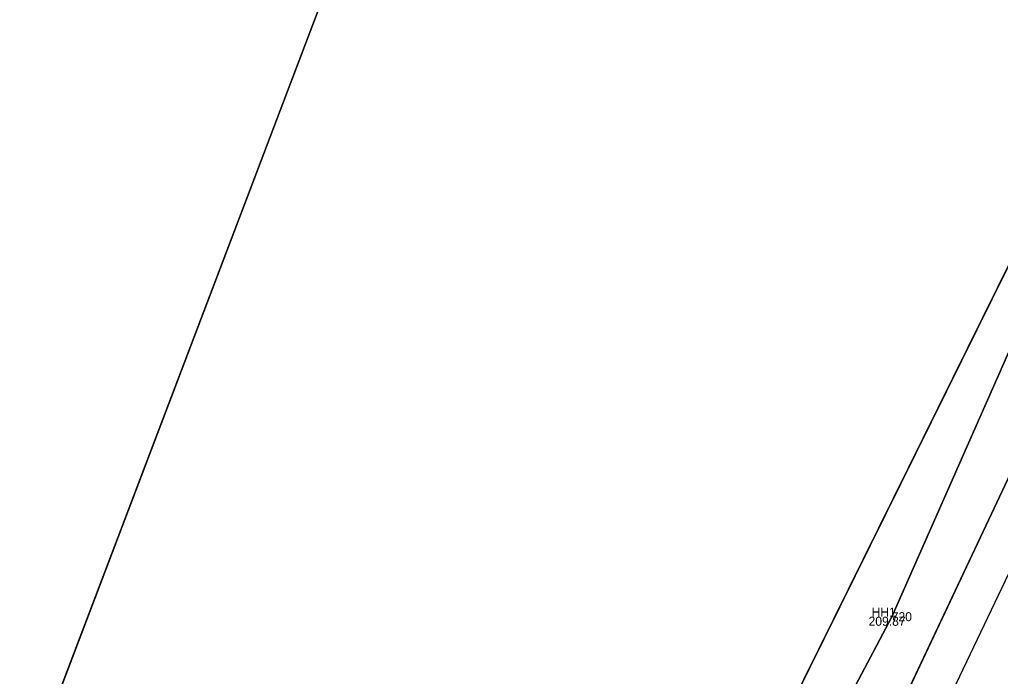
# Model space of a CAD drawing. Extents: x -263091 to -262565, y -1238731 to -1237092.
# Drawn here: x -262808.34 to -262786.65, y -1237663.71 to -1237649.19 of the extents above; entities that cross this region are included whole.
import ezdxf

# ---------------------------------------------------------------- set-up
doc = ezdxf.new("R2010")
doc.units = 0
for name, color, linetype in [('01_Hrana_betónu', 7, 'Continuous'), ('02_Oplotenie', 7, 'Continuous'), ('05_Hrana_terénu', 7, 'Continuous'), ('11_Hranica_KN', 7, 'Continuous'), ('Groma (21)', 7, 'Continuous'), ('Groma (22)', 7, 'Continuous'), ('Groma (23)', 7, 'Continuous'), ('Groma (24)', 7, 'Continuous'), ('U005_Betónové_panely', 7, 'Continuous'), ('U005_Zeleň_mimo', 7, 'Continuous'), ('U005_Zeleň_vnútro', 7, 'Continuous'), ('U005_Zeleň_zatrávňovač', 7, 'Continuous')]:
    doc.layers.add(name, color=color, linetype=linetype)

msp = doc.modelspace()

# ---------------------------------------------------------------- linework, layer by layer
at = {"layer": '01_Hrana_betónu'}
for points in [[(-262744.671, -1237314.693), (-262744.322, -1237332.28), (-262744.032, -1237356.103), (-262743.621, -1237377.876), (-262743.427, -1237401.834), (-262743.334, -1237423.507), (-262743.665, -1237455.163), (-262743.89, -1237458.66), (-262743.816, -1237479.543), (-262744.125, -1237500.374), (-262744.256, -1237524.891), (-262744.407, -1237545.149), (-262744.747, -1237556.085), (-262745.544, -1237564.593), (-262746.648, -1237572.023), (-262748.879, -1237581.03), (-262752.099, -1237589.665), (-262756.673, -1237599.828), (-262765.314, -1237617.226), (-262775.804, -1237639.013), (-262783.576, -1237655.372), (-262792.033, -1237673.09)], [(-262792.676, -1237672.47), (-262784.421, -1237654.971), (-262776.677, -1237638.569), (-262766.087, -1237616.912), (-262757.487, -1237599.378), (-262752.942, -1237589.379), (-262749.712, -1237580.796), (-262747.504, -1237571.715), (-262746.486, -1237564.414), (-262745.673, -1237555.98), (-262745.336, -1237545.322), (-262745.216, -1237524.737), (-262745.016, -1237500.506), (-262744.745, -1237479.418), (-262744.873, -1237458.479), (-262744.515, -1237455.206), (-262744.284, -1237423.517), (-262744.408, -1237401.828), (-262744.521, -1237377.717), (-262744.916, -1237356.111), (-262745.155, -1237332.402), (-262745.296, -1237327.881), (-262745.213, -1237324.651), (-262745.472, -1237315.175)]]:
    msp.add_lwpolyline(points, dxfattribs=at)
at = {"layer": '02_Oplotenie'}
msp.add_lwpolyline([(-262793.971, -1237669.784), (-262786.051, -1237653.784), (-262778.339, -1237638.096), (-262767.839, -1237615.998), (-262759.49, -1237598.413), (-262754.828, -1237588.44), (-262751.768, -1237579.927), (-262749.971, -1237571.226), (-262749.021, -1237564.318), (-262748.215, -1237555.413), (-262747.787, -1237545.2), (-262747.818, -1237524.565), (-262747.681, -1237500.551), (-262747.391, -1237479.445), (-262747.231, -1237460.146), (-262746.875, -1237423.458), (-262747.304, -1237401.954), (-262748.156, -1237377.36), (-262748.89, -1237356.224), (-262749.247, -1237329.045)], dxfattribs=at)
at = {"layer": '05_Hrana_terénu'}
msp.add_lwpolyline([(-262746.684, -1237500.449), (-262746.883, -1237524.672), (-262746.96, -1237545.219), (-262747.259, -1237555.728), (-262748.105, -1237564.398), (-262749.066, -1237571.186), (-262750.795, -1237580.085), (-262754.134, -1237588.771), (-262758.577, -1237598.887), (-262767.121, -1237616.464), (-262785.488, -1237654.334), (-262789.051, -1237662.387), (-262794.016, -1237671.765)], dxfattribs=at)
at = {"layer": '11_Hranica_KN'}
msp.add_lwpolyline([(-262808.336, -1237666.357), (-262793.39, -1237627.04), (-262791.777, -1237622.951)], dxfattribs=at)
at = {"layer": 'Groma (21)'}
msp.add_circle((-262789.051, -1237662.387), 0.01, dxfattribs=at)
at = {"layer": 'U005_Betónové_panely'}
for points in [[(-262783.28, -1237678.88), (-262786.97, -1237677.03), (-262787.74, -1237676.65), (-262788.17, -1237676.43), (-262788.97, -1237676.03), (-262792.52, -1237674.26), (-262791.95, -1237673.18), (-262792.03, -1237673.09), (-262792.68, -1237672.47), (-262784.42, -1237654.97), (-262776.68, -1237638.57), (-262766.09, -1237616.91), (-262757.49, -1237599.38), (-262752.94, -1237589.38), (-262749.71, -1237580.8), (-262747.5, -1237571.72), (-262746.49, -1237564.41), (-262745.67, -1237555.98), (-262745.34, -1237545.32), (-262745.22, -1237524.74), (-262745.02, -1237500.51)], [(-262747.21, -1237604.2), (-262756.24, -1237623.63), (-262765.96, -1237644.11), (-262773.68, -1237660.32), (-262779.99, -1237673.1), (-262781.45, -1237675.8), (-262782.33, -1237677.96), (-262782.75, -1237677.74), (-262783.28, -1237678.88), (-262786.97, -1237677.03), (-262787.74, -1237676.65), (-262788.17, -1237676.43), (-262788.97, -1237676.03), (-262792.52, -1237674.26), (-262791.95, -1237673.18), (-262792.03, -1237673.09), (-262792.68, -1237672.47), (-262784.42, -1237654.97), (-262776.68, -1237638.57), (-262766.09, -1237616.91)]]:
    msp.add_lwpolyline(points, dxfattribs=at)
at = {"layer": 'U005_Zeleň_mimo'}
msp.add_lwpolyline([(-262747.68, -1237500.55), (-262747.82, -1237524.57), (-262747.79, -1237545.2), (-262748.22, -1237555.41), (-262749.02, -1237564.32), (-262749.97, -1237571.23), (-262751.77, -1237579.93), (-262754.83, -1237588.44), (-262759.49, -1237598.41), (-262767.84, -1237616), (-262778.34, -1237638.1), (-262786.05, -1237653.78), (-262793.97, -1237669.78), (-262795.54, -1237672.75), (-262808.34, -1237666.36), (-262793.39, -1237627.04), (-262791.78, -1237622.95), (-262787.11, -1237623.75), (-262784.13, -1237624.4), (-262781.33, -1237608.15), (-262778.14, -1237587.84), (-262773.94, -1237562.14), (-262768.34, -1237527.64), (-262757.02, -1237455.96)], dxfattribs=at)
at = {"layer": 'U005_Zeleň_vnútro'}
for points in [[(-262794.83, -1237673.1), (-262795.54, -1237672.75), (-262793.97, -1237669.78), (-262786.05, -1237653.78), (-262778.34, -1237638.1), (-262767.84, -1237616), (-262759.49, -1237598.41), (-262754.83, -1237588.44), (-262751.77, -1237579.93), (-262749.97, -1237571.23), (-262749.02, -1237564.32), (-262748.22, -1237555.41), (-262747.79, -1237545.2), (-262747.82, -1237524.57), (-262747.68, -1237500.55)], [(-262746.68, -1237500.45), (-262746.88, -1237524.67), (-262746.96, -1237545.22), (-262747.26, -1237555.73), (-262748.11, -1237564.4), (-262749.07, -1237571.19), (-262750.8, -1237580.09), (-262754.13, -1237588.77), (-262758.58, -1237598.89), (-262767.12, -1237616.46), (-262785.49, -1237654.33), (-262789.05, -1237662.39), (-262794.02, -1237671.77), (-262794.42, -1237672.24), (-262794.83, -1237673.1)], [(-262767.12, -1237616.46), (-262785.49, -1237654.33), (-262789.05, -1237662.39), (-262794.02, -1237671.77), (-262794.42, -1237672.24), (-262794.83, -1237673.1), (-262795.54, -1237672.75), (-262793.97, -1237669.78), (-262786.05, -1237653.78), (-262778.34, -1237638.1), (-262767.84, -1237616)]]:
    msp.add_lwpolyline(points, dxfattribs=at)
at = {"layer": 'U005_Zeleň_zatrávňovač'}
for points in [[(-262792.68, -1237672.47), (-262792.92, -1237672.24), (-262794.02, -1237671.77), (-262789.05, -1237662.39), (-262785.49, -1237654.33), (-262767.12, -1237616.46), (-262758.58, -1237598.89), (-262754.13, -1237588.77), (-262750.8, -1237580.09), (-262749.07, -1237571.19), (-262748.11, -1237564.4), (-262747.26, -1237555.73), (-262746.96, -1237545.22), (-262746.88, -1237524.67), (-262746.68, -1237500.45)], [(-262745.02, -1237500.51), (-262745.22, -1237524.74), (-262745.34, -1237545.32), (-262745.67, -1237555.98), (-262746.49, -1237564.41), (-262747.5, -1237571.72), (-262749.71, -1237580.8), (-262752.94, -1237589.38), (-262757.49, -1237599.38), (-262766.09, -1237616.91), (-262776.68, -1237638.57), (-262784.42, -1237654.97), (-262792.68, -1237672.47)], [(-262766.09, -1237616.91), (-262776.68, -1237638.57), (-262784.42, -1237654.97), (-262792.68, -1237672.47), (-262792.92, -1237672.24), (-262794.02, -1237671.77), (-262789.05, -1237662.39), (-262785.49, -1237654.33), (-262767.12, -1237616.46)]]:
    msp.add_lwpolyline(points, dxfattribs=at)

# ---------------------------------------------------------------- texts
at = {"layer": 'Groma (22)'}
msp.add_text('720', height=0.2, dxfattribs=at).set_placement((-262789.051, -1237662.487))
at = {"layer": 'Groma (23)'}
msp.add_text('209.87', height=0.2, dxfattribs=at).set_placement((-262789.564, -1237662.587))
at = {"layer": 'Groma (24)'}
msp.add_text('HH1', height=0.2, dxfattribs=at).set_placement((-262789.498, -1237662.387))

doc.saveas('drawing.dxf')
